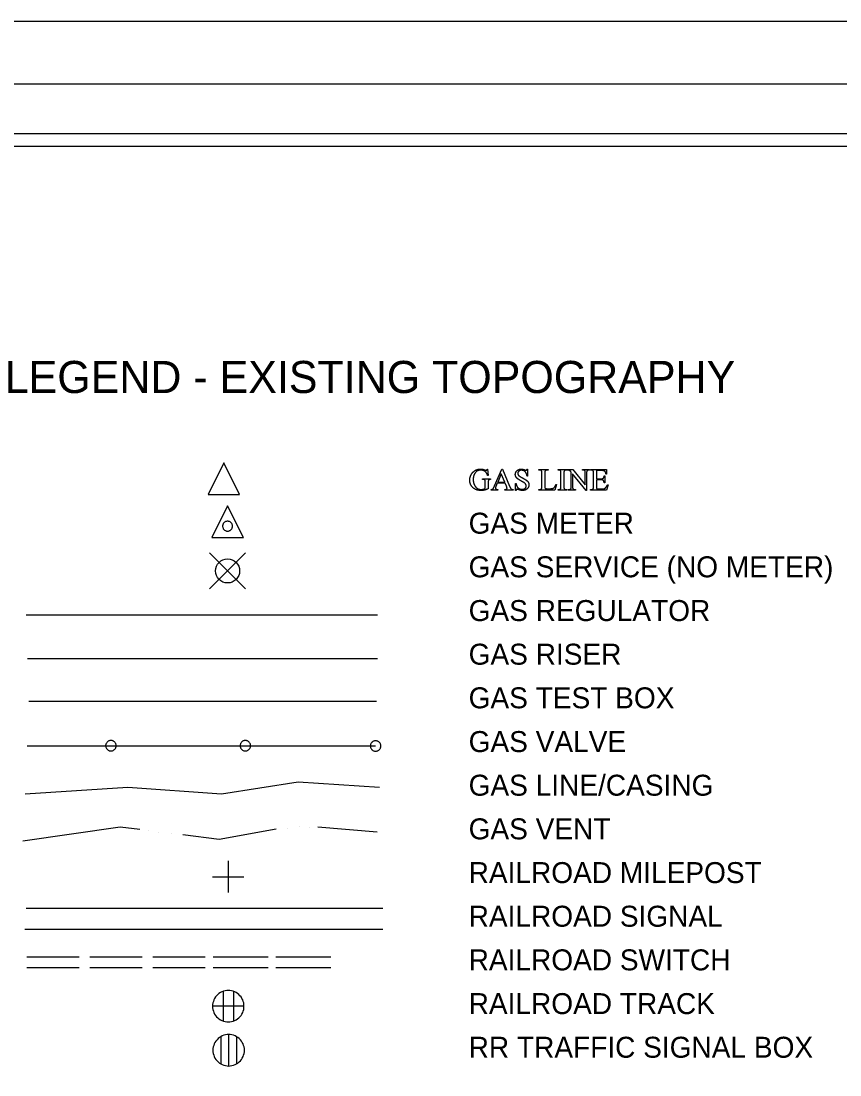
# Model space of a CAD drawing. Extents: x -1.93 to 2.83, y -1.79 to 1.85.
# Drawn here: x 0.366 to 0.638, y 1.4831 to 1.8333 of the extents above; entities that cross this region are included whole.
import ezdxf

# ---------------------------------------------------------------- set-up
doc = ezdxf.new("R2010")
doc.units = 0
for name, color, linetype in [('Legend', 7, 'Continuous'), ('Plot Border', 7, 'Continuous'), ('Plot Border 2', 7, 'Continuous'), ('Sheet Border', 7, 'Continuous')]:
    doc.layers.add(name, color=color, linetype=linetype)

msp = doc.modelspace()

# ---------------------------------------------------------------- linework, layer by layer
at = {"layer": 'Legend'}
for p, q in [((0.42861, 1.64461), (0.44061, 1.65661)), ((0.44061, 1.64461), (0.42861, 1.65661)), ((0.36775, 1.636), (0.48442, 1.636)), ((0.36817, 1.62146), (0.48442, 1.62146)), ((0.36858, 1.60738), (0.48408, 1.60738)), ((0.36804, 1.59245), (0.48375, 1.59245)), ((0.43258, 1.5765), (0.458, 1.58054)), ((0.458, 1.58054), (0.48508, 1.57879)), ((0.36742, 1.5765), (0.40146, 1.57879)), ((0.40146, 1.57879), (0.43258, 1.5765)), ((0.36662, 1.56093), (0.39892, 1.56556)), ((0.39892, 1.56556), (0.40546, 1.56476)), ((0.45837, 1.56576), (0.45837, 1.56576)), ((0.46454, 1.56556), (0.48433, 1.56385)), ((0.40833, 1.56422), (0.40833, 1.56422)), ((0.41175, 1.56372), (0.41175, 1.56372)), ((0.41596, 1.56322), (0.41596, 1.56322)), ((0.41971, 1.56301), (0.43183, 1.56151)), ((0.43183, 1.56151), (0.45079, 1.56489)), ((0.45446, 1.56506), (0.45446, 1.56506)), ((0.46191, 1.56539), (0.46191, 1.56539)), ((0.36767, 1.53851), (0.48617, 1.53851)), ((0.36729, 1.53159), (0.48617, 1.53159)), ((0.36796, 1.52232), (0.38537, 1.52232)), ((0.38883, 1.52232), (0.40625, 1.52232)), ((0.40975, 1.52232), (0.42717, 1.52232)), ((0.42981, 1.52232), (0.44722, 1.52232)), ((0.43067, 1.52232), (0.44808, 1.52232)), ((0.45062, 1.52232), (0.46803, 1.52232)), ((0.45148, 1.52232), (0.46889, 1.52232)), ((0.36796, 1.51886), (0.38537, 1.51886)), ((0.38883, 1.51886), (0.40625, 1.51886)), ((0.40975, 1.51886), (0.42717, 1.51886)), ((0.42981, 1.51886), (0.44722, 1.51886)), ((0.43067, 1.51886), (0.44808, 1.51886)), ((0.45062, 1.51886), (0.46803, 1.51886)), ((0.45148, 1.51886), (0.46889, 1.51886))]:
    msp.add_line(p, q, dxfattribs=at)
for points in [[(0.4334, 1.68651), (0.42815, 1.67605), (0.43861, 1.67605), (0.4334, 1.68651)], [(0.51931, 1.68103), (0.51931, 1.68121), (0.52194, 1.68121), (0.52194, 1.68103), (0.52182, 1.68103)], [(0.52079, 1.68446), (0.52098, 1.68446)], [(0.52098, 1.68446), (0.52115, 1.68231), (0.52098, 1.68231)], [(0.52329, 1.67886), (0.52569, 1.68446), (0.52587, 1.68446), (0.52824, 1.67879)], [(0.52666, 1.68014), (0.52551, 1.68289), (0.52432, 1.68014), (0.52666, 1.68014)], [(0.53425, 1.68446), (0.53425, 1.68211), (0.53407, 1.68211)], [(0.53407, 1.68446), (0.53425, 1.68446)], [(0.53828, 1.68412), (0.53802, 1.68412), (0.53802, 1.6843), (0.5411, 1.6843), (0.5411, 1.68412)], [(0.539, 1.6787), (0.539, 1.6831)], [(0.53996, 1.68298), (0.53996, 1.6787)], [(0.54459, 1.68412), (0.54435, 1.68412), (0.54435, 1.6843), (0.54726, 1.6843), (0.54726, 1.68412), (0.54702, 1.68412)], [(0.54533, 1.6787), (0.54533, 1.6831)], [(0.54629, 1.6831), (0.54629, 1.6787)], [(0.54739, 1.6843), (0.54923, 1.6843), (0.5534, 1.67919), (0.5534, 1.68312)], [(0.54739, 1.68412), (0.54739, 1.6843)], [(0.54873, 1.67867), (0.54873, 1.68341)], [(0.55384, 1.68312), (0.55384, 1.67738), (0.55366, 1.67738), (0.54917, 1.68287), (0.54917, 1.67867)], [(0.55267, 1.68412), (0.55244, 1.68412), (0.55244, 1.6843), (0.5548, 1.6843), (0.5548, 1.68412), (0.55456, 1.68412)], [(0.5554, 1.68412), (0.55516, 1.68412), (0.55516, 1.6843), (0.56042, 1.6843), (0.56049, 1.68281), (0.56029, 1.68281)], [(0.55614, 1.6787), (0.55614, 1.68312)], [(0.5571, 1.68393), (0.5571, 1.68124), (0.5586, 1.68124)], [(0.55897, 1.68393), (0.5571, 1.68393)], [(0.55967, 1.68223), (0.55985, 1.68223), (0.55985, 1.67986), (0.55967, 1.67986)], [(0.5202, 1.67805), (0.5202, 1.68002)], [(0.52118, 1.68002), (0.52118, 1.67794)], [(0.52432, 1.67768), (0.52432, 1.67749), (0.52217, 1.67749), (0.52217, 1.67768)], [(0.52681, 1.67977), (0.52416, 1.67977), (0.5237, 1.6787)], [(0.52941, 1.67768), (0.52941, 1.67749), (0.52673, 1.67749), (0.52673, 1.67768)], [(0.52722, 1.67879), (0.52681, 1.67977)], [(0.53042, 1.67734), (0.53024, 1.67734), (0.53024, 1.67967), (0.53042, 1.67967)], [(0.54371, 1.67938), (0.54388, 1.67934), (0.54329, 1.67749), (0.53802, 1.67749), (0.53802, 1.67768), (0.53828, 1.67768)], [(0.54101, 1.67793), (0.54151, 1.67793)], [(0.54726, 1.67768), (0.54726, 1.67749), (0.54435, 1.67749), (0.54435, 1.67768), (0.54459, 1.67768)], [(0.54702, 1.67768), (0.54726, 1.67768)], [(0.54989, 1.67768), (0.55013, 1.67768), (0.55013, 1.67749), (0.54777, 1.67749), (0.54777, 1.67768), (0.548, 1.67768)], [(0.5608, 1.6792), (0.561, 1.6792), (0.56041, 1.67749), (0.55516, 1.67749), (0.55516, 1.67768), (0.5554, 1.67768)], [(0.5586, 1.68087), (0.5571, 1.68087), (0.5571, 1.67863)], [(0.55766, 1.67787), (0.55882, 1.67787)], [(0.4346, 1.6722), (0.42939, 1.66174), (0.43985, 1.66174), (0.4346, 1.6722)], [(0.4346, 1.66711), (0.43443, 1.66711), (0.43426, 1.66707), (0.4341, 1.66703), (0.43393, 1.66699), (0.43381, 1.6669), (0.43364, 1.66682), (0.43351, 1.6667), (0.43339, 1.66657), (0.43326, 1.66645), (0.43318, 1.66632), (0.4331, 1.66615), (0.43306, 1.66599), (0.43301, 1.66582), (0.43297, 1.66565), (0.43297, 1.66549), (0.43297, 1.66532), (0.43301, 1.66515), (0.43306, 1.66499), (0.4331, 1.66482), (0.43318, 1.66465), (0.43326, 1.66453), (0.43339, 1.66436), (0.43351, 1.66424), (0.43364, 1.66415), (0.43381, 1.66407), (0.43393, 1.66399), (0.4341, 1.6639), (0.43426, 1.66386), (0.43443, 1.66382), (0.4346, 1.66382), (0.43476, 1.66382), (0.43497, 1.66386), (0.4351, 1.6639), (0.43526, 1.66399), (0.43543, 1.66407), (0.4356, 1.66415), (0.43572, 1.66424), (0.43585, 1.66436), (0.43593, 1.66453), (0.43606, 1.66465), (0.4361, 1.66482), (0.43618, 1.66499), (0.43622, 1.66515), (0.43626, 1.66532), (0.43626, 1.66549), (0.43626, 1.66565), (0.43622, 1.66582), (0.43618, 1.66599), (0.4361, 1.66615), (0.43606, 1.66632), (0.43593, 1.66645), (0.43585, 1.66657), (0.43572, 1.6667), (0.4356, 1.66682), (0.43543, 1.6669), (0.43526, 1.66699), (0.4351, 1.66703), (0.43497, 1.66707), (0.43476, 1.66711), (0.4346, 1.66711)], [(0.39587, 1.59078), (0.39604, 1.59078), (0.39625, 1.59082), (0.39642, 1.59086), (0.39658, 1.5909), (0.39675, 1.59099), (0.39687, 1.59111), (0.39704, 1.59124), (0.39717, 1.59136), (0.39729, 1.59149), (0.39737, 1.59165), (0.39746, 1.59182), (0.39754, 1.59199), (0.39758, 1.59215), (0.39758, 1.59232), (0.39762, 1.59253), (0.39758, 1.5927), (0.39758, 1.59286), (0.39754, 1.59303), (0.39746, 1.59324), (0.39737, 1.59336), (0.39729, 1.59353), (0.39717, 1.5937), (0.39704, 1.59382), (0.39687, 1.5939), (0.39675, 1.59403), (0.39658, 1.59411), (0.39642, 1.59415), (0.39625, 1.5942), (0.39604, 1.59424), (0.39587, 1.59424), (0.39571, 1.59424), (0.3955, 1.5942), (0.39533, 1.59415), (0.39517, 1.59411), (0.395, 1.59403), (0.39483, 1.5939), (0.39471, 1.59382), (0.39458, 1.5937), (0.39446, 1.59353), (0.39437, 1.59336), (0.39429, 1.59324), (0.39421, 1.59303), (0.39417, 1.59286), (0.39412, 1.5927), (0.39412, 1.59253), (0.39412, 1.59232), (0.39417, 1.59215), (0.39421, 1.59199), (0.39429, 1.59182), (0.39437, 1.59165), (0.39446, 1.59149), (0.39458, 1.59136), (0.39471, 1.59124), (0.39483, 1.59111), (0.395, 1.59099), (0.39517, 1.5909), (0.39533, 1.59086), (0.3955, 1.59082), (0.39571, 1.59078), (0.39587, 1.59078)], [(0.4405, 1.59078), (0.44071, 1.59078), (0.44087, 1.59082), (0.44104, 1.59086), (0.44121, 1.5909), (0.44137, 1.59099), (0.44154, 1.59111), (0.44167, 1.59124), (0.44179, 1.59136), (0.44192, 1.59149), (0.44204, 1.59165), (0.44212, 1.59182), (0.44217, 1.59199), (0.44221, 1.59215), (0.44225, 1.59232), (0.44225, 1.59253), (0.44225, 1.5927), (0.44221, 1.59286), (0.44217, 1.59303), (0.44212, 1.59324), (0.44204, 1.59336), (0.44192, 1.59353), (0.44179, 1.5937), (0.44167, 1.59382), (0.44154, 1.5939), (0.44137, 1.59403), (0.44121, 1.59411), (0.44104, 1.59415), (0.44087, 1.5942), (0.44071, 1.59424), (0.4405, 1.59424), (0.44033, 1.59424), (0.44017, 1.5942), (0.43996, 1.59415), (0.43979, 1.59411), (0.43962, 1.59403), (0.4395, 1.5939), (0.43933, 1.59382), (0.43921, 1.5937), (0.43912, 1.59353), (0.439, 1.59336), (0.43892, 1.59324), (0.43887, 1.59303), (0.43879, 1.59286), (0.43879, 1.5927), (0.43879, 1.59253), (0.43879, 1.59232), (0.43879, 1.59215), (0.43887, 1.59199), (0.43892, 1.59182), (0.439, 1.59165), (0.43912, 1.59149), (0.43921, 1.59136), (0.43933, 1.59124), (0.4395, 1.59111), (0.43962, 1.59099), (0.43979, 1.5909), (0.43996, 1.59086), (0.44017, 1.59082), (0.44033, 1.59078), (0.4405, 1.59078)], [(0.48375, 1.5907), (0.48396, 1.5907), (0.48412, 1.59074), (0.48429, 1.59078), (0.48446, 1.59082), (0.48462, 1.5909), (0.48479, 1.59103), (0.48492, 1.59115), (0.48504, 1.59128), (0.48517, 1.5914), (0.48529, 1.59157), (0.48537, 1.59174), (0.48542, 1.5919), (0.48546, 1.59207), (0.4855, 1.59224), (0.4855, 1.59245), (0.4855, 1.59261), (0.48546, 1.59278), (0.48542, 1.59299), (0.48537, 1.59315), (0.48529, 1.59332), (0.48517, 1.59345), (0.48504, 1.59361), (0.48492, 1.59374), (0.48479, 1.59382), (0.48462, 1.59395), (0.48446, 1.59403), (0.48429, 1.59407), (0.48412, 1.59415), (0.48396, 1.59415), (0.48375, 1.59415), (0.48358, 1.59415), (0.48342, 1.59415), (0.48321, 1.59407), (0.48304, 1.59403), (0.48287, 1.59395), (0.48275, 1.59382), (0.48258, 1.59374), (0.48246, 1.59361), (0.48237, 1.59345), (0.48225, 1.59332), (0.48217, 1.59315), (0.48212, 1.59299), (0.48204, 1.59278), (0.48204, 1.59261), (0.48204, 1.59245), (0.48204, 1.59224), (0.48204, 1.59207), (0.48212, 1.5919), (0.48217, 1.59174), (0.48225, 1.59157), (0.48237, 1.5914), (0.48246, 1.59128), (0.48258, 1.59115), (0.48275, 1.59103), (0.48287, 1.5909), (0.48304, 1.59082), (0.48321, 1.59078), (0.48342, 1.59074), (0.48358, 1.5907), (0.48375, 1.5907)], [(0.43481, 1.55424), (0.43481, 1.54378)], [(0.4296, 1.54899), (0.44006, 1.54899)], [(0.43485, 1.50074), (0.43539, 1.50078), (0.43593, 1.50086), (0.43647, 1.50099), (0.43697, 1.50119), (0.43747, 1.50144), (0.43793, 1.50174), (0.43835, 1.50207), (0.43872, 1.50244), (0.4391, 1.5029), (0.43939, 1.50336), (0.43964, 1.50382), (0.43981, 1.50436), (0.43997, 1.50486), (0.44006, 1.5054), (0.44006, 1.50594), (0.44006, 1.50653), (0.43997, 1.50703), (0.43981, 1.50757), (0.43964, 1.50807), (0.43939, 1.50857), (0.4391, 1.50903), (0.43872, 1.50944), (0.43835, 1.50986), (0.43793, 1.51019), (0.43747, 1.51049), (0.43697, 1.51074), (0.43647, 1.51094), (0.43593, 1.51107), (0.43539, 1.51115), (0.43485, 1.51119), (0.43431, 1.51115), (0.43376, 1.51107), (0.43322, 1.51094), (0.43272, 1.51074), (0.43222, 1.51049), (0.43176, 1.51019), (0.43135, 1.50986), (0.43097, 1.50944), (0.43064, 1.50903), (0.43031, 1.50857), (0.4301, 1.50807), (0.42989, 1.50757), (0.42972, 1.50703), (0.42964, 1.50653), (0.42964, 1.50594), (0.42964, 1.5054), (0.42972, 1.50486), (0.42989, 1.50436), (0.4301, 1.50382), (0.43031, 1.50336), (0.43064, 1.5029), (0.43097, 1.50244), (0.43135, 1.50207), (0.43176, 1.50174), (0.43222, 1.50144), (0.43272, 1.50119), (0.43322, 1.50099), (0.43376, 1.50086), (0.43431, 1.50078), (0.43485, 1.50074)], [(0.43314, 1.5109), (0.43314, 1.50103)], [(0.4366, 1.5109), (0.4366, 1.50103)], [(0.44006, 1.50594), (0.42964, 1.50594)], [(0.43497, 1.49654), (0.43443, 1.4965), (0.43389, 1.49642), (0.43335, 1.49629), (0.43285, 1.49608), (0.43235, 1.49583), (0.43189, 1.49554), (0.43147, 1.49521), (0.4311, 1.49483), (0.43076, 1.49438), (0.43043, 1.49392), (0.43018, 1.49346), (0.43001, 1.49292), (0.42985, 1.49242), (0.42976, 1.49188), (0.42976, 1.49133), (0.42976, 1.49079), (0.42985, 1.49025), (0.43001, 1.48971), (0.43018, 1.48921), (0.43043, 1.48871), (0.43076, 1.48825), (0.4311, 1.48783), (0.43147, 1.48746), (0.43189, 1.48708), (0.43235, 1.48679), (0.43285, 1.48654), (0.43335, 1.48633), (0.43389, 1.48621), (0.43443, 1.48613), (0.43497, 1.48608), (0.43551, 1.48613), (0.43606, 1.48621), (0.4366, 1.48633), (0.4371, 1.48654), (0.4376, 1.48679), (0.43806, 1.48708), (0.43847, 1.48746), (0.43885, 1.48783), (0.43918, 1.48825), (0.43951, 1.48871), (0.43976, 1.48921), (0.43993, 1.48971), (0.4401, 1.49025), (0.44018, 1.49079), (0.44018, 1.49133), (0.44018, 1.49188), (0.4401, 1.49242), (0.43993, 1.49292), (0.43976, 1.49346), (0.43951, 1.49392), (0.43918, 1.49438), (0.43885, 1.49483), (0.43847, 1.49521), (0.43806, 1.49554), (0.4376, 1.49583), (0.4371, 1.49608), (0.4366, 1.49629), (0.43606, 1.49642), (0.43551, 1.4965), (0.43497, 1.49654)], [(0.43239, 1.49583), (0.43239, 1.48679)], [(0.43497, 1.49654), (0.43497, 1.48608)], [(0.4376, 1.49583), (0.4376, 1.48679)]]:
    msp.add_lwpolyline(points, dxfattribs=at)
msp.add_circle((0.43461, 1.65061), 0.004, dxfattribs=at)
for points in [[(0.51503, 1.68079), (0.51503, 1.68169), (0.51546, 1.68252)], [(0.51546, 1.68252), (0.51597, 1.68349), (0.51686, 1.68402)], [(0.51675, 1.68307), (0.51618, 1.6822), (0.51618, 1.681)], [(0.51873, 1.6841), (0.51742, 1.6841), (0.51675, 1.68307)], [(0.51686, 1.68402), (0.51761, 1.68446), (0.51863, 1.68446)], [(0.51863, 1.68446), (0.519, 1.68446), (0.51931, 1.6844)], [(0.52029, 1.68352), (0.51968, 1.6841), (0.51873, 1.6841)], [(0.51931, 1.6844), (0.51961, 1.68434), (0.52017, 1.68413)], [(0.52017, 1.68413), (0.52045, 1.68403), (0.52055, 1.68403)], [(0.52098, 1.68231), (0.52071, 1.68311), (0.52029, 1.68352)], [(0.52055, 1.68403), (0.52064, 1.68403), (0.52071, 1.68411)], [(0.52071, 1.68411), (0.52078, 1.6842), (0.52079, 1.68446)], [(0.53017, 1.68267), (0.53017, 1.6834), (0.53073, 1.68393)], [(0.53036, 1.68189), (0.53017, 1.68224), (0.53017, 1.68267)], [(0.53092, 1.68125), (0.53055, 1.68154), (0.53036, 1.68189)], [(0.53073, 1.68393), (0.5313, 1.68446), (0.53217, 1.68446)], [(0.53217, 1.68047), (0.53129, 1.68096), (0.53092, 1.68125)], [(0.53131, 1.68374), (0.53097, 1.68342), (0.53097, 1.68301)], [(0.53097, 1.68301), (0.53097, 1.6827), (0.53119, 1.68245)], [(0.53119, 1.68245), (0.5315, 1.68207), (0.53267, 1.68144)], [(0.53218, 1.68406), (0.53165, 1.68406), (0.53131, 1.68374)], [(0.53217, 1.68446), (0.53271, 1.68446), (0.53332, 1.68419)], [(0.53308, 1.68382), (0.53264, 1.68406), (0.53218, 1.68406)], [(0.53267, 1.68144), (0.53363, 1.68093), (0.53398, 1.68065)], [(0.53374, 1.68318), (0.53351, 1.68359), (0.53308, 1.68382)], [(0.53332, 1.68419), (0.5336, 1.68407), (0.53372, 1.68407)], [(0.53372, 1.68407), (0.53385, 1.68407), (0.53394, 1.68415)], [(0.53407, 1.68211), (0.53398, 1.68278), (0.53374, 1.68318)], [(0.53394, 1.68415), (0.53402, 1.68422), (0.53407, 1.68446)], [(0.53886, 1.6839), (0.53866, 1.68412), (0.53828, 1.68412)], [(0.539, 1.6831), (0.539, 1.68374), (0.53886, 1.6839)], [(0.54004, 1.68375), (0.53996, 1.68359), (0.53996, 1.68298)], [(0.54034, 1.68402), (0.54012, 1.68391), (0.54004, 1.68375)], [(0.5411, 1.68412), (0.54056, 1.68412), (0.54034, 1.68402)], [(0.54505, 1.684), (0.54483, 1.68412), (0.54459, 1.68412)], [(0.54526, 1.68378), (0.54521, 1.68391), (0.54505, 1.684)], [(0.54533, 1.6831), (0.54533, 1.68362), (0.54526, 1.68378)], [(0.54641, 1.68387), (0.54629, 1.68371), (0.54629, 1.6831)], [(0.54702, 1.68412), (0.5466, 1.68412), (0.54641, 1.68387)], [(0.54783, 1.68407), (0.54769, 1.68412), (0.54739, 1.68412)], [(0.54828, 1.68387), (0.54813, 1.68398), (0.54783, 1.68407)], [(0.54873, 1.68341), (0.54843, 1.68376), (0.54828, 1.68387)], [(0.55326, 1.68391), (0.55307, 1.68412), (0.55267, 1.68412)], [(0.5534, 1.68312), (0.5534, 1.68375), (0.55326, 1.68391)], [(0.55395, 1.68386), (0.55384, 1.6837), (0.55384, 1.68312)], [(0.55456, 1.68412), (0.55413, 1.68412), (0.55395, 1.68386)], [(0.55601, 1.68392), (0.55583, 1.68412), (0.5554, 1.68412)], [(0.55614, 1.68312), (0.55614, 1.68377), (0.55601, 1.68392)], [(0.5586, 1.68124), (0.55918, 1.68124), (0.55938, 1.68142)], [(0.55968, 1.68385), (0.55948, 1.68393), (0.55897, 1.68393)], [(0.55938, 1.68142), (0.55964, 1.68165), (0.55967, 1.68223)], [(0.56006, 1.68355), (0.55993, 1.68375), (0.55968, 1.68385)], [(0.56029, 1.68281), (0.56019, 1.68335), (0.56006, 1.68355)], [(0.51579, 1.6786), (0.51503, 1.67955), (0.51503, 1.68079)], [(0.51879, 1.67734), (0.51682, 1.67734), (0.51579, 1.6786)], [(0.51618, 1.681), (0.51618, 1.68003), (0.51656, 1.67923)], [(0.51656, 1.67923), (0.51693, 1.67842), (0.51754, 1.67805)], [(0.51754, 1.67805), (0.51815, 1.67768), (0.5188, 1.67768)], [(0.5188, 1.67768), (0.51917, 1.67768), (0.51952, 1.67777)], [(0.51988, 1.68094), (0.51972, 1.68103), (0.51931, 1.68103)], [(0.51952, 1.67777), (0.51988, 1.67787), (0.5202, 1.67805)], [(0.52012, 1.6807), (0.52005, 1.68086), (0.51988, 1.68094)], [(0.52118, 1.67794), (0.5206, 1.67763), (0.52004, 1.67748)], [(0.5202, 1.68002), (0.5202, 1.68054), (0.52012, 1.6807)], [(0.52128, 1.68076), (0.52118, 1.68058), (0.52118, 1.68002)], [(0.52182, 1.68103), (0.52143, 1.68103), (0.52128, 1.68076)], [(0.52217, 1.67768), (0.5226, 1.67775), (0.52272, 1.67787)], [(0.52272, 1.67787), (0.52298, 1.67811), (0.52329, 1.67886)], [(0.5237, 1.6787), (0.52353, 1.6783), (0.52353, 1.6781)], [(0.52353, 1.6781), (0.52353, 1.67795), (0.52368, 1.67783)], [(0.52368, 1.67783), (0.52383, 1.67771), (0.52432, 1.67768)], [(0.52673, 1.67768), (0.52713, 1.6777), (0.52728, 1.67781)], [(0.52742, 1.67809), (0.52742, 1.67831), (0.52722, 1.67879)], [(0.52728, 1.67781), (0.52742, 1.67793), (0.52742, 1.67809)], [(0.52824, 1.67879), (0.52853, 1.67811), (0.52876, 1.6779)], [(0.52876, 1.6779), (0.529, 1.6777), (0.52941, 1.67768)], [(0.53042, 1.67967), (0.53055, 1.67894), (0.53078, 1.67857)], [(0.53053, 1.67765), (0.53046, 1.67757), (0.53042, 1.67734)], [(0.53073, 1.67773), (0.5306, 1.67773), (0.53053, 1.67765)], [(0.53135, 1.67757), (0.53086, 1.67773), (0.53073, 1.67773)], [(0.53078, 1.67857), (0.531, 1.67821), (0.53145, 1.67797)], [(0.532, 1.67738), (0.53184, 1.67741), (0.53135, 1.67757)], [(0.53145, 1.67797), (0.53191, 1.67773), (0.53245, 1.67773)], [(0.53324, 1.67983), (0.53304, 1.67998), (0.53217, 1.68047)], [(0.53245, 1.67773), (0.53308, 1.67773), (0.53344, 1.67806)], [(0.5341, 1.6779), (0.5335, 1.67734), (0.53256, 1.67734)], [(0.53367, 1.67935), (0.53353, 1.67961), (0.53324, 1.67983)], [(0.53344, 1.67806), (0.53381, 1.67839), (0.53381, 1.67884)], [(0.53381, 1.67884), (0.53381, 1.6791), (0.53367, 1.67935)], [(0.53398, 1.68065), (0.53433, 1.68038), (0.53451, 1.68001)], [(0.5347, 1.67923), (0.5347, 1.67846), (0.5341, 1.6779)], [(0.53451, 1.68001), (0.5347, 1.67964), (0.5347, 1.67923)], [(0.53828, 1.67768), (0.53871, 1.67768), (0.53889, 1.67796)], [(0.53889, 1.67796), (0.539, 1.67812), (0.539, 1.6787)], [(0.53996, 1.6787), (0.53996, 1.67829), (0.54004, 1.67813)], [(0.54004, 1.67813), (0.5401, 1.67803), (0.54023, 1.67798)], [(0.54023, 1.67798), (0.54035, 1.67793), (0.54101, 1.67793)], [(0.54151, 1.67793), (0.54229, 1.67793), (0.54261, 1.67804)], [(0.54261, 1.67804), (0.54293, 1.67816), (0.54319, 1.67845)], [(0.54319, 1.67845), (0.54345, 1.67875), (0.54371, 1.67938)], [(0.54459, 1.67768), (0.54501, 1.67768), (0.54521, 1.67792)], [(0.54521, 1.67792), (0.54533, 1.67808), (0.54533, 1.6787)], [(0.54629, 1.6787), (0.54629, 1.67818), (0.54635, 1.67801)], [(0.54635, 1.67801), (0.5464, 1.67789), (0.54656, 1.6778)], [(0.54656, 1.6778), (0.54678, 1.67768), (0.54702, 1.67768)], [(0.548, 1.67768), (0.54844, 1.67768), (0.54862, 1.67794)], [(0.54862, 1.67794), (0.54873, 1.6781), (0.54873, 1.67867)], [(0.54917, 1.67867), (0.54917, 1.67804), (0.54931, 1.67789)], [(0.54931, 1.67789), (0.5495, 1.67768), (0.54989, 1.67768)], [(0.5554, 1.67768), (0.55565, 1.67768), (0.55586, 1.67779)], [(0.55586, 1.67779), (0.55602, 1.67787), (0.55608, 1.67804)], [(0.55608, 1.67804), (0.55614, 1.6782), (0.55614, 1.6787)], [(0.5571, 1.67863), (0.5571, 1.67818), (0.55714, 1.67808)], [(0.55714, 1.67808), (0.55718, 1.67798), (0.55728, 1.67792)], [(0.55728, 1.67792), (0.55738, 1.67787), (0.55766, 1.67787)], [(0.55923, 1.68077), (0.55903, 1.68087), (0.5586, 1.68087)], [(0.55882, 1.67787), (0.5594, 1.67787), (0.55966, 1.67795)], [(0.55953, 1.68049), (0.55944, 1.68067), (0.55923, 1.68077)], [(0.55967, 1.67986), (0.5596, 1.68035), (0.55953, 1.68049)], [(0.55966, 1.67795), (0.55992, 1.67803), (0.56016, 1.67826)], [(0.56016, 1.67826), (0.56047, 1.67857), (0.5608, 1.6792)], [(0.52004, 1.67748), (0.51948, 1.67734), (0.51879, 1.67734)], [(0.53256, 1.67734), (0.53226, 1.67734), (0.532, 1.67738)]]:
    msp.add_open_spline(points, degree=2, dxfattribs=at)
at = {"layer": 'Plot Border'}
for points in [[(0, 1.83333), (2.83333, 1.83333), (2.83333, 0), (0, 0)], [(2.825, 1.79583), (0.075, 1.79583), (0.075, 0.0375), (2.825, 0.0375)]]:
    msp.add_lwpolyline(points, close=True, dxfattribs=at)
at = {"layer": 'Plot Border 2'}
msp.add_lwpolyline([(0, 1.8125), (2.83333, 1.8125), (2.83333, 0.02083), (0, 0.02083)], close=True, dxfattribs=at)
at = {"layer": 'Sheet Border'}
msp.add_line((2.81667, 1.79167), (0.19167, 1.79167), dxfattribs=at)

# ---------------------------------------------------------------- texts
at = {"layer": 'Legend'}
for s, height, p in [('GAS METER', 0.006967, (0.51467, 1.66299)), ('GAS SERVICE (NO METER)', 0.0069667, (0.51467, 1.64849)), ('GAS REGULATOR', 0.0069667, (0.51467, 1.63395)), ('GAS RISER', 0.006967, (0.51467, 1.61945)), ('GAS TEST BOX', 0.0069667, (0.51467, 1.60495)), ('GAS VALVE', 0.006967, (0.51467, 1.59041)), ('GAS LINE/CASING', 0.0069667, (0.51467, 1.57591)), ('GAS VENT', 0.006967, (0.51467, 1.56141)), ('RAILROAD MILEPOST', 0.0069667, (0.51467, 1.54687)), ('RAILROAD SIGNAL', 0.0069667, (0.51467, 1.53237)), ('RAILROAD SWITCH', 0.0069667, (0.51467, 1.51787)), ('RAILROAD TRACK', 0.0069667, (0.51467, 1.50333)), ('RR TRAFFIC SIGNAL BOX', 0.0069667, (0.51467, 1.48883))]:
    msp.add_text(s, height=height, dxfattribs=at).set_placement(p)
at = {"layer": 'Sheet Border'}
msp.add_text('LEGEND - EXISTING TOPOGRAPHY', height=0.01067, dxfattribs=at).set_placement((0.3606, 1.70972))

doc.saveas('drawing.dxf')
